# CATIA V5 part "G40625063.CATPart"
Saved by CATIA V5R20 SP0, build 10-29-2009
Part number: G40625063
Revision: 4
Definition: design
Nomenclature: G40625063
Source: made
Description: NOT SPECIFIED
Bounding box of the stored display mesh (mm): x -31.5 to 31.5, y -25 to 0, z -10 to 10
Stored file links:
  C:\Users\Raffaele\Desktop\3D X SITO CF\BOLEX\30-GUIDE STRIP REF 406\G40625063.CATPart
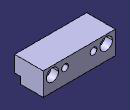
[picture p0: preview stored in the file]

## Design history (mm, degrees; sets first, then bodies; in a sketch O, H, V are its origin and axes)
Body1 "MANIFOLD_SOLID_BREP #2440" (main body)
  Solid1: solid without history
Body2 "MANIFOLD_SOLID_BREP #2578"
  Solid2: solid without history
Body3 "MANIFOLD_SOLID_BREP #2690"
  Solid3: solid without history
Body4 "MANIFOLD_SOLID_BREP #2802"
  Solid4: solid without history
Body5 "MANIFOLD_SOLID_BREP #2914"
  Solid5: solid without history
Body6 "MANIFOLD_SOLID_BREP #3026"
  Solid6: solid without history
Body7 "MANIFOLD_SOLID_BREP #3138"
  Solid7: solid without history
Body8 "MANIFOLD_SOLID_BREP #3250"
  Solid8: solid without history
Body9 "MANIFOLD_SOLID_BREP #3388"
  Solid9: solid without history
Body10 "MANIFOLD_SOLID_BREP #3526"
  Solid10: solid without history
Body11 "MANIFOLD_SOLID_BREP #3664"
  Solid11: solid without history
Body12 "MANIFOLD_SOLID_BREP #3802"
  Solid12: solid without history
Body13 "MANIFOLD_SOLID_BREP #3914"
  Solid13: solid without history
Body14 "MANIFOLD_SOLID_BREP #4026"
  Solid14: solid without history
Body15 "MANIFOLD_SOLID_BREP #4138"
  Solid15: solid without history
Body16 "MANIFOLD_SOLID_BREP #4250"
  Solid16: solid without history
Body17 "MANIFOLD_SOLID_BREP #4362"
  Solid17: solid without history
Body18 "MANIFOLD_SOLID_BREP #4474"
  Solid18: solid without history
